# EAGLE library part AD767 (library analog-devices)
ANALOG DEVICES
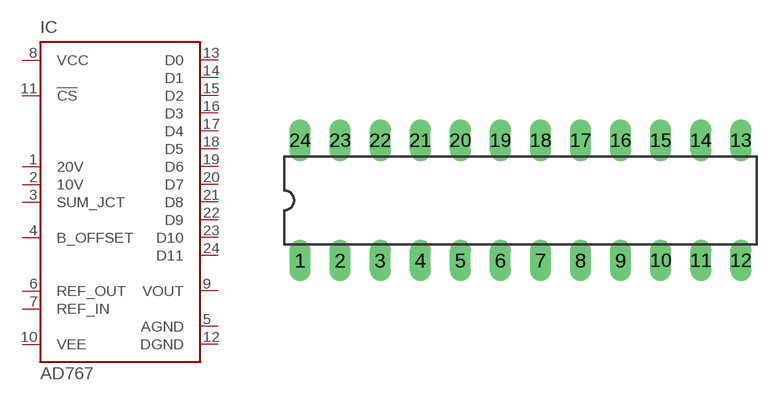
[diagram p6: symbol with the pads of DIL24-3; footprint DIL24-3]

Designator prefix IC

## AD767 (MF: ALTERA CORPORATION; MPN: AD767KNZ; OC_FARNELL: 9604510; OC_NEWARK: 59K5176)  [DIL24-3]
1  20V  pas
2  10V  pas
3  SUM_JCT  pas
4  B_OFFSET  pas
5  AGND  pwr
6  REF_OUT  out
7  REF_IN  in
8  VCC  pwr
9  VOUT  out
10  VEE  pwr
11  !CS  in
12  DGND  pwr
13  D0  hiz
14  D1  hiz
15  D2  hiz
16  D3  hiz
17  D4  hiz
18  D5  hiz
19  D6  hiz
20  D7  hiz
21  D8  hiz
22  D9  hiz
23  D10  hiz
24  D11  hiz

## Footprint DIL24-3 (pad centres in mm)
Dual In Line Package 0.3 inch
drill 0.813 long: 1 -13.97,-3.81; 2 -11.43,-3.81; 3 -8.89,-3.81; 4 -6.35,-3.81; 5 -3.81,-3.81; 6 -1.27,-3.81; 7 1.27,-3.81; 8 3.81,-3.81; 9 6.35,-3.81; 10 8.89,-3.81; 11 11.43,-3.81; 12 13.97,-3.81; 13 13.97,3.81; 14 11.43,3.81; 15 8.89,3.81; 16 6.35,3.81; 17 3.81,3.81; 18 1.27,3.81; 19 -1.27,3.81; 20 -3.81,3.81; 21 -6.35,3.81; 22 -8.89,3.81; 23 -11.43,3.81; 24 -13.97,3.81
